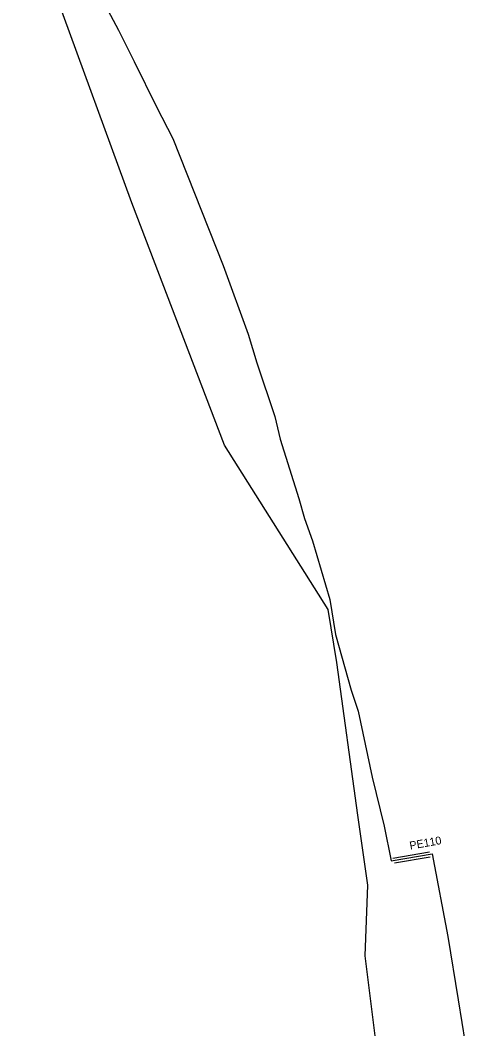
# Model space of a CAD drawing. Extents: x -731967 to -723173, y -945358 to -941505.
# Drawn here: x -725843.7 to -725787.5, y -942497.5 to -942371.5 of the extents above; entities that cross this region are included whole.
import ezdxf

# ---------------------------------------------------------------- set-up
doc = ezdxf.new("R2010")
doc.units = 0
for name, color, linetype in [('Vrstva 2', 7, 'Continuous'), ('Vrstva 28', 7, 'Continuous'), ('Vrstva 35', 7, 'Continuous')]:
    doc.layers.add(name, color=color, linetype=linetype)

msp = doc.modelspace()

# ---------------------------------------------------------------- linework, layer by layer
at = {"layer": 'Vrstva 2'}
for points in [[(-725797.19, -942476.17), (-725792.63, -942475.38)], [(-725797.19, -942476.17), (-725792.63, -942475.38)], [(-725796.98, -942476.74), (-725792.53, -942475.97)], [(-725796.98, -942476.74), (-725792.53, -942475.97)]]:
    msp.add_lwpolyline(points, dxfattribs=at)
at = {"layer": 'Vrstva 28'}
for points in [[(-725843.7, -942351.31), (-725842, -942354), (-725839.13, -942359.21), (-725837.26, -942362.1), (-725833.78, -942368.36), (-725831.42, -942372.76), (-725829.46, -942376.68), (-725826.7, -942382.34), (-725824.65, -942386.3), (-725818.36, -942402.14), (-725815.26, -942410.73), (-725814.18, -942414.28), (-725811.95, -942421.01), (-725811.25, -942423.82), (-725808.92, -942431.23), (-725808.24, -942433.75), (-725807.25, -942436.52), (-725805.06, -942443.84), (-725804.36, -942448.24), (-725802.42, -942455.17), (-725801.53, -942457.81), (-725799.8, -942466.03), (-725798.31, -942472.16)], [(-725843.7, -942351.31), (-725842, -942354), (-725839.13, -942359.21), (-725837.26, -942362.1), (-725833.78, -942368.36), (-725831.42, -942372.76), (-725829.46, -942376.68), (-725826.7, -942382.34), (-725824.65, -942386.3), (-725818.36, -942402.14), (-725815.26, -942410.73), (-725814.18, -942414.28), (-725811.95, -942421.01), (-725811.25, -942423.82), (-725808.92, -942431.23), (-725808.24, -942433.75), (-725807.25, -942436.52), (-725805.06, -942443.84), (-725804.36, -942448.24), (-725802.42, -942455.17), (-725801.53, -942457.81), (-725799.8, -942466.03), (-725798.31, -942472.16)], [(-725798.31, -942472.16), (-725797.43, -942476.51), (-725792.29, -942475.63), (-725790.34, -942485.93), (-725789.07, -942493.86), (-725788.6, -942496.7), (-725787.48, -942503.69)], [(-725798.31, -942472.16), (-725797.43, -942476.51), (-725792.29, -942475.63), (-725790.34, -942485.93), (-725789.07, -942493.86), (-725788.6, -942496.7), (-725787.48, -942503.69)]]:
    msp.add_lwpolyline(points, dxfattribs=at)
at = {"layer": 'Vrstva 35'}
for p, q in [((-725829.77, -942394.31), (-725839.96, -942366.38)), ((-725818.21, -942424.58), (-725829.77, -942394.31)), ((-725805.26, -942445.11), (-725818.21, -942424.58)), ((-725804.2, -942451.74), (-725805.26, -942445.11)), ((-725801.56, -942470.77), (-725804.2, -942451.74)), ((-725800.34, -942479.53), (-725801.56, -942470.77)), ((-725800.68, -942488.36), (-725800.34, -942479.53)), ((-725797.37, -942514.48), (-725800.68, -942488.36))]:
    msp.add_line(p, q, dxfattribs=at)

# ---------------------------------------------------------------- texts
at = {"layer": 'Vrstva 2'}
msp.add_text('PE110', height=1, rotation=10.1874, dxfattribs=at).set_placement((-725795.03, -942475.1))
msp.add_text('PE110', height=1, rotation=10.1874, dxfattribs=at).set_placement((-725795.03, -942475.1))

doc.saveas('drawing.dxf')
